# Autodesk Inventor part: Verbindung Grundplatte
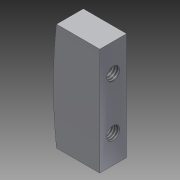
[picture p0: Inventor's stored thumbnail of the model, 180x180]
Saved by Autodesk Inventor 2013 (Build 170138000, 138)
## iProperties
Created: 2012-10
Part Number: Verbindung Grundplatte
Material: Aluminium 6061
Document SubType Name: Modeling
Designer: Marvin
Density: 2.71 g/cm^3
Mass: 8.43438 g
Surface Area: 16.6692 cm^2
Volume: 3.11232 cm^3
Author: Marvin
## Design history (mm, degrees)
sketch "Skizze3" dims "d30" = 158
  geometry: L1 (86.423, 10)-(78.365, 10); L2 (78.365, 10)-(78.365, -10); L3 (78.365, -10)-(86.423, -10); A1 r 87 centre (0, 0) between (86.423, -10) and (86.423, 10); 2 further points
  constraints: 6 end point, 2 coincident, 2 point on circle, 1 centre point, 1 horizontal, 1 parallel, 1 perpendicular, 1 vertical alignment, 3 other
  dimensions: "d0" = 87 radius of A1; "d2" = 20 distance of L1.end L2.end
extrude "Extrusion1" new body sketch "Skizze3" stored distance "d4" = 5; taper "d5" = 0 deg
sketch "Skizze5" dims "d28" = 166
  geometry: L1 (121.8, 0)-(-121.8, 0) reference; C1 r 79 at (0, 0); C2 r 87 at (0, 0); A1 r 87 centre (0, 0) between (-86.423, 10) and (-86.423, -10) reference; 2 further points
  constraints: 3 coincident, 2 centre point, 1 horizontal alignment, 1 point on line, 2 other
  dimensions: "d26" = 158 diameter of C1; "d27" = 174 diameter of C2
hole "Bohrung2" sketch "Skizze5" at (-83, 0) diameter "d18" = 3; stored, may be unused: countersink angle "d22" = 90 deg, drill point angle "d24" = 118 deg; dims "d19" = 6, "d20" = 4, "d21" = 2, "d23" = 3
sketch "Skizze6"
  geometry: L1 (0, 0)-(86.838, 5.311); L2 (0, 0)-(86.838, -5.311); L3 (-121.8, 0)-(121.8, 0) reference; A1 r 87 centre (0, 0) between (86.838, 5.311) and (86.838, -5.311); 1 further point
  constraints: 4 end point, 2 point on circle, 1 centre point, 1 coincident
  dimensions: "d40" = 174 diameter of A1; "d41" = 3.5 deg angle of L1 L3; "d43" = 3.5 deg angle of L3 L2 (= d41)
workplane "Arbeitsebene1"
workplane "Arbeitsebene2"
sketch "Skizze7"
  geometry: 2 further points
  constraints: 1 coincident
hole "Bohrung4" sketch "Skizze7" at (0, 0) diameter "d47" = 2.459; stored, may be unused: countersink angle "d51" = 90 deg, drill point angle "d53" = 118 deg; dims "d48" = 6, "d49" = 4, "d50" = 2, "d52" = 8
sketch "Skizze8"
  geometry: 2 further points
  constraints: 1 coincident
hole "Bohrung5" sketch "Skizze8" at (0, 0) diameter "d54" = 2.459; stored, may be unused: countersink angle "d58" = 90 deg, drill point angle "d60" = 118 deg; dims "d55" = 6, "d56" = 4, "d57" = 2, "d59" = 8
node "Volumenkörper1"
